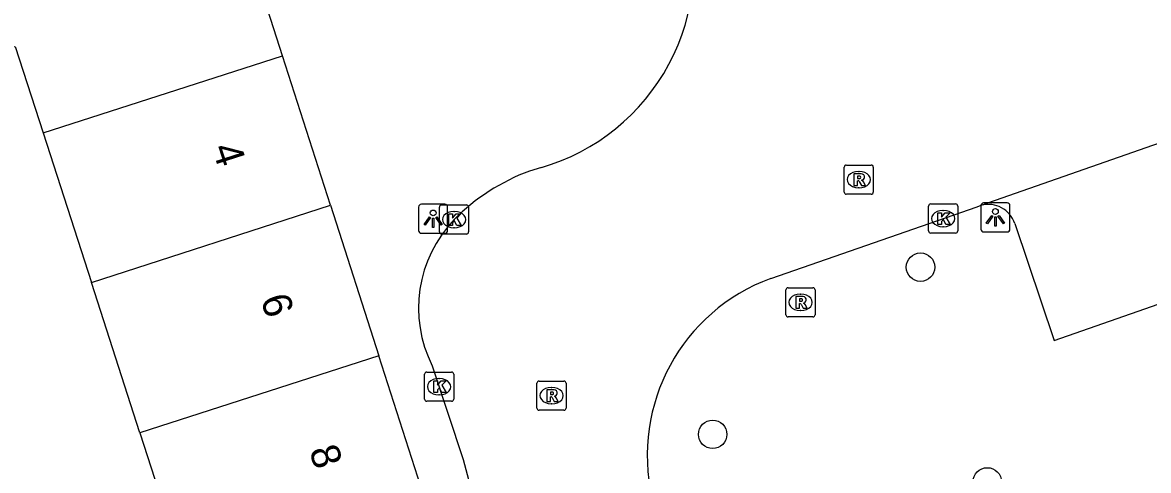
# Model space of a CAD drawing. Extents: x 159377 to 159983, y 382996 to 383595.
# Drawn here: x 159562.92 to 159601.57, y 383270.37 to 383285.73 of the extents above; entities that cross this region are included whole.
import ezdxf

# ---------------------------------------------------------------- set-up
doc = ezdxf.new("R2010")
doc.units = 0
for name, color, linetype in [('IMGEO_Boom', 7, 'Continuous'), ('IMGEO_Kolk', 7, 'Continuous'), ('IMGEO_Lichtpunt', 7, 'Continuous'), ('IMGEO_Pand', 7, 'Continuous'), ('IMGEO_Pand_nummerreeks', 7, 'Continuous'), ('IMGEO_Rijbaan_lokaal_open', 7, 'Continuous'), ('IMGEO_Rioolput', 7, 'Continuous'), ('IMGEO_Voetpad_open', 7, 'Continuous')]:
    doc.layers.add(name, color=color, linetype=linetype)

msp = doc.modelspace()

# ---------------------------------------------------------------- linework, layer by layer
at = {"layer": 'IMGEO_Boom'}
for centre in [(159593.747, 383277.342), (159586.612, 383271.606), (159596.038, 383269.973)]:
    msp.add_circle(centre, 0.489, dxfattribs=at)
at = {"layer": 'IMGEO_Kolk'}
for p, q in [((159577.307, 383279.475), (159578.159, 383279.475)), ((159594.024, 383278.583), (159594.024, 383279.435)), ((159594.099, 383279.509), (159594.951, 383279.509)), ((159595.025, 383279.435), (159595.025, 383278.583)), ((159577.232, 383278.549), (159577.232, 383279.401)), ((159577.72, 383279.255), (159577.745, 383279.255)), ((159578.233, 383279.401), (159578.233, 383278.549)), ((159594.512, 383279.289), (159594.537, 383279.289)), ((159577.743, 383278.695), (159577.718, 383278.695)), ((159594.535, 383278.729), (159594.51, 383278.729)), ((159578.159, 383278.475), (159577.307, 383278.475)), ((159594.951, 383278.509), (159594.099, 383278.509)), ((159576.72, 383272.814), (159576.72, 383273.666)), ((159576.795, 383273.74), (159577.647, 383273.74)), ((159577.721, 383273.666), (159577.721, 383272.814)), ((159577.208, 383273.52), (159577.233, 383273.52)), ((159577.231, 383272.96), (159577.206, 383272.96)), ((159577.647, 383272.74), (159576.795, 383272.74))]:
    msp.add_line(p, q, dxfattribs=at)
for points in [[(159577.307, 383279.475), (159578.159, 383279.475)], [(159594.024, 383278.583), (159594.024, 383279.435)], [(159594.099, 383279.509), (159594.951, 383279.509)], [(159595.025, 383279.435), (159595.025, 383278.583)], [(159577.232, 383278.549), (159577.232, 383279.401)], [(159577.553, 383279.175), (159577.676, 383279.175), (159577.676, 383279.024), (159577.806, 383279.175), (159577.97, 383279.175), (159577.824, 383279.024), (159577.977, 383278.775), (159577.825, 383278.775), (159577.74, 383278.939), (159577.676, 383278.872), (159577.676, 383278.775), (159577.553, 383278.775), (159577.553, 383279.175)], [(159578.233, 383279.401), (159578.233, 383278.549)], [(159594.345, 383279.209), (159594.468, 383279.209), (159594.468, 383279.058), (159594.598, 383279.209), (159594.762, 383279.209), (159594.616, 383279.058), (159594.769, 383278.809), (159594.617, 383278.809), (159594.532, 383278.973), (159594.468, 383278.906), (159594.468, 383278.809), (159594.345, 383278.809), (159594.345, 383279.209)], [(159578.159, 383278.475), (159577.307, 383278.475)], [(159594.951, 383278.509), (159594.099, 383278.509)], [(159576.72, 383272.814), (159576.72, 383273.666)], [(159576.795, 383273.74), (159577.647, 383273.74)], [(159577.721, 383273.666), (159577.721, 383272.814)], [(159577.041, 383273.44), (159577.164, 383273.44), (159577.164, 383273.289), (159577.294, 383273.44), (159577.458, 383273.44), (159577.312, 383273.289), (159577.465, 383273.04), (159577.313, 383273.04), (159577.228, 383273.204), (159577.164, 383273.137), (159577.164, 383273.04), (159577.041, 383273.04), (159577.041, 383273.44)], [(159577.647, 383272.74), (159576.795, 383272.74)]]:
    msp.add_lwpolyline(points, dxfattribs=at)
for centre, start, end in [((159577.309, 383279.399), 91.552, 178.448), ((159577.309, 383279.399), 91.552, 178.448), ((159578.157, 383279.399), 1.552, 88.448), ((159578.157, 383279.399), 1.552, 88.448), ((159594.101, 383279.433), 91.552, 178.448), ((159594.101, 383279.433), 91.552, 178.448), ((159594.949, 383279.433), 1.552, 88.448), ((159594.949, 383279.433), 1.552, 88.448), ((159577.309, 383278.551), 181.552, 268.448), ((159577.309, 383278.551), 181.552, 268.448), ((159578.157, 383278.551), 271.552, 358.448), ((159578.157, 383278.551), 271.552, 358.448), ((159594.101, 383278.585), 181.552, 268.448), ((159594.101, 383278.585), 181.552, 268.448), ((159594.949, 383278.585), 271.552, 358.448), ((159594.949, 383278.585), 271.552, 358.448), ((159576.797, 383273.664), 91.552, 178.448), ((159576.797, 383273.664), 91.552, 178.448), ((159577.645, 383273.664), 1.552, 88.448), ((159577.645, 383273.664), 1.552, 88.448), ((159576.797, 383272.816), 181.552, 268.448), ((159576.797, 383272.816), 181.552, 268.448), ((159577.645, 383272.816), 271.552, 358.448), ((159577.645, 383272.816), 271.552, 358.448)]:
    msp.add_arc(centre, 0.0765, start, end, dxfattribs=at)
for centre, major_axis, ratio, start_param, end_param in [((159577.719, 383278.975), (-0.387, 0.002), 0.722429, 4.712389, 7.853982), ((159577.744, 383278.975), (-0.39, 0.002), 0.717154, 1.570796, 4.712389), ((159594.511, 383279.009), (-0.387, 0.002), 0.722429, 4.712389, 7.853982), ((159594.536, 383279.009), (-0.39, 0.002), 0.717154, 1.570796, 4.712389), ((159577.207, 383273.24), (-0.387, 0.002), 0.722429, 4.712389, 7.853982), ((159577.232, 383273.24), (-0.39, 0.002), 0.717154, 1.570796, 4.712389)]:
    msp.add_ellipse(centre, major_axis=major_axis, ratio=ratio, start_param=start_param, end_param=end_param, dxfattribs=at)
at = {"layer": 'IMGEO_Lichtpunt'}
for p, q in [((159577.418, 383279.499), (159576.61, 383279.499)), ((159577.418, 383279.499), (159576.61, 383279.499)), ((159595.819, 383279.452), (159595.819, 383278.645)), ((159595.819, 383279.452), (159595.819, 383278.645)), ((159596.721, 383279.547), (159595.913, 383279.547)), ((159596.721, 383279.547), (159595.913, 383279.547)), ((159596.815, 383278.645), (159596.815, 383279.452)), ((159596.815, 383278.645), (159596.815, 383279.452)), ((159576.516, 383279.404), (159576.516, 383278.597)), ((159576.516, 383279.404), (159576.516, 383278.597)), ((159577.512, 383278.597), (159577.512, 383279.404)), ((159577.512, 383278.597), (159577.512, 383279.404)), ((159576.61, 383278.503), (159577.418, 383278.503)), ((159576.61, 383278.503), (159577.418, 383278.503)), ((159595.913, 383278.551), (159596.721, 383278.551)), ((159595.913, 383278.551), (159596.721, 383278.551))]:
    msp.add_line(p, q, dxfattribs=at)
for points in [[(159576.89, 383279.068), (159576.929, 383279.04), (159576.741, 383278.778), (159576.703, 383278.805), (159576.89, 383279.068)], [(159577.102, 383279.04), (159577.14, 383279.067), (159577.327, 383278.805), (159577.288, 383278.777), (159577.102, 383279.04)], [(159596.193, 383279.116), (159596.232, 383279.088), (159596.044, 383278.826), (159596.006, 383278.853), (159596.193, 383279.116)], [(159596.295, 383279.068), (159596.342, 383279.068), (159596.342, 383278.746), (159596.295, 383278.746), (159596.295, 383279.068)], [(159596.405, 383279.088), (159596.443, 383279.115), (159596.63, 383278.853), (159596.591, 383278.825), (159596.405, 383279.088)], [(159576.992, 383279.02), (159577.039, 383279.02), (159577.039, 383278.698), (159576.992, 383278.698), (159576.992, 383279.02)]]:
    msp.add_lwpolyline(points, dxfattribs=at)
for centre in [(159577.015, 383279.202), (159596.318, 383279.25)]:
    msp.add_circle(centre, 0.0994, dxfattribs=at)
for centre, start, end in [((159576.61, 383279.404), 90, 180), ((159576.61, 383279.404), 90, 180), ((159577.418, 383279.404), 0, 90), ((159577.418, 383279.404), 0, 90), ((159595.913, 383279.452), 90, 180), ((159595.913, 383279.452), 90, 180), ((159596.721, 383279.452), 0, 90), ((159596.721, 383279.452), 0, 90), ((159595.913, 383278.645), 180, 270), ((159595.913, 383278.645), 180, 270), ((159596.721, 383278.645), 270, 0), ((159596.721, 383278.645), 270, 360), ((159576.61, 383278.597), 180, 270), ((159576.61, 383278.597), 180, 270), ((159577.418, 383278.597), 270, 0), ((159577.418, 383278.597), 270, 360)]:
    msp.add_arc(centre, 0.0946, start, end, dxfattribs=at)
at = {"layer": 'IMGEO_Pand'}
for points in [[(159571.843, 383284.598), (159570.124, 383289.948)], [(159560.137, 383286.727), (159560.895, 383284.428), (159562.668, 383284.918), (159563.625, 383281.952)], [(159563.625, 383281.952), (159571.843, 383284.598)], [(159573.492, 383279.466), (159571.843, 383284.598)], [(159563.625, 383281.952), (159565.282, 383276.82)], [(159565.282, 383276.82), (159573.492, 383279.466)], [(159573.492, 383279.466), (159575.151, 383274.304)], [(159566.947, 383271.661), (159565.282, 383276.82)], [(159575.151, 383274.304), (159566.947, 383271.661)], [(159576.801, 383269.171), (159575.151, 383274.304)], [(159566.947, 383271.661), (159568.603, 383266.531)]]:
    msp.add_lwpolyline(points, dxfattribs=at)
at = {"layer": 'IMGEO_Rijbaan_lokaal_open'}
for points in [[(159595.831, 383279.464), (159630.111, 383291.458)], [(159580.733, 383280.762), (159580.321, 383280.639)], [(159588.61, 383276.954), (159595.694, 383279.416), (159595.831, 383279.464)], [(159576.984, 383273.96), (159578.044, 383270.742), (159578.879, 383267.605)]]:
    msp.add_lwpolyline(points, dxfattribs=at)
for centre, radius, start, end in [((159578.704, 383287.742), 7.269, 286.2109, 17.3819), ((159582.878, 383273.818), 7.285, 110.5479, 134.9315), ((159580.896, 383275.939), 4.384, 136.1765, 206.8346), ((159590.818, 383270.893), 6.451, 110.0178, 193.0148)]:
    msp.add_arc(centre, radius, start, end, dxfattribs=at)
at = {"layer": 'IMGEO_Rioolput'}
for p, q in [((159591.125, 383279.92), (159591.125, 383280.772)), ((159591.2, 383280.846), (159592.052, 383280.846)), ((159591.613, 383280.626), (159591.638, 383280.626)), ((159592.126, 383280.772), (159592.126, 383279.92)), ((159592.052, 383279.846), (159591.2, 383279.846)), ((159591.636, 383280.066), (159591.611, 383280.066)), ((159589.127, 383275.709), (159589.127, 383276.561)), ((159589.202, 383276.635), (159590.054, 383276.635)), ((159589.615, 383276.415), (159589.64, 383276.415)), ((159590.128, 383276.561), (159590.128, 383275.709)), ((159590.054, 383275.635), (159589.202, 383275.635)), ((159589.638, 383275.855), (159589.613, 383275.855)), ((159580.579, 383272.509), (159580.579, 383273.361)), ((159580.654, 383273.435), (159581.506, 383273.435)), ((159581.58, 383273.361), (159581.58, 383272.509)), ((159581.067, 383273.215), (159581.092, 383273.215)), ((159581.09, 383272.655), (159581.065, 383272.655)), ((159581.506, 383272.435), (159580.654, 383272.435))]:
    msp.add_line(p, q, dxfattribs=at)
for points in [[(159591.125, 383279.92), (159591.125, 383280.772)], [(159591.2, 383280.846), (159592.052, 383280.846)], [(159592.126, 383280.772), (159592.126, 383279.92)], [(159591.714, 383280.544), (159591.462, 383280.546), (159591.462, 383280.146)], [(159591.462, 383280.146), (159591.586, 383280.146), (159591.586, 383280.308), (159591.597, 383280.308)], [(159591.64, 383280.465), (159591.586, 383280.465), (159591.586, 383280.384)], [(159591.586, 383280.384), (159591.638, 383280.384)], [(159591.644, 383280.279), (159591.715, 383280.146), (159591.855, 383280.146), (159591.79, 383280.272)], [(159592.052, 383279.846), (159591.2, 383279.846)], [(159589.127, 383275.709), (159589.127, 383276.561)], [(159589.202, 383276.635), (159590.054, 383276.635)], [(159589.716, 383276.333), (159589.464, 383276.335), (159589.464, 383275.935)], [(159590.128, 383276.561), (159590.128, 383275.709)], [(159589.464, 383275.935), (159589.588, 383275.935), (159589.588, 383276.097), (159589.599, 383276.097)], [(159589.642, 383276.254), (159589.588, 383276.254), (159589.588, 383276.173)], [(159589.588, 383276.173), (159589.64, 383276.173)], [(159589.646, 383276.068), (159589.717, 383275.935), (159589.857, 383275.935), (159589.792, 383276.061)], [(159590.054, 383275.635), (159589.202, 383275.635)], [(159580.579, 383272.509), (159580.579, 383273.361)], [(159580.654, 383273.435), (159581.506, 383273.435)], [(159581.58, 383273.361), (159581.58, 383272.509)], [(159581.168, 383273.133), (159580.916, 383273.135), (159580.916, 383272.735)], [(159580.916, 383272.735), (159581.04, 383272.735), (159581.04, 383272.897), (159581.051, 383272.897)], [(159581.094, 383273.054), (159581.04, 383273.054), (159581.04, 383272.973)], [(159581.04, 383272.973), (159581.092, 383272.973)], [(159581.098, 383272.868), (159581.169, 383272.735), (159581.309, 383272.735), (159581.244, 383272.861)], [(159581.506, 383272.435), (159580.654, 383272.435)]]:
    msp.add_lwpolyline(points, dxfattribs=at)
for centre, radius, start, end in [((159591.202, 383280.77), 0.0765, 91.552, 178.448), ((159591.202, 383280.77), 0.0765, 91.552, 178.448), ((159592.05, 383280.77), 0.0765, 1.552, 88.448), ((159592.05, 383280.77), 0.0765, 1.552, 88.448), ((159591.596, 383280.255), 0.0533, 26.0293, 88.6989), ((159591.622, 383280.573), 0.19, 274.7715, 282.9687), ((159591.646, 383280.369), 0.0964, 77.0061, 93.1865), ((159591.66, 383280.426), 0.0378, 276.6634, 79.6772), ((159591.713, 383280.434), 0.109, 350.3612, 89.416), ((159591.711, 383280.434), 0.112, 277.5842, 350.9817), ((159591.695, 383280.219), 0.108, 29.5134, 73.7905), ((159591.202, 383279.922), 0.0765, 181.552, 268.448), ((159591.202, 383279.922), 0.0765, 181.552, 268.448), ((159592.05, 383279.922), 0.0765, 271.552, 358.448), ((159592.05, 383279.922), 0.0765, 271.552, 358.448), ((159589.204, 383276.559), 0.0765, 91.552, 178.448), ((159589.204, 383276.559), 0.0765, 91.552, 178.448), ((159589.715, 383276.223), 0.109, 350.3612, 89.416), ((159590.052, 383276.559), 0.0765, 1.552, 88.448), ((159590.052, 383276.559), 0.0765, 1.552, 88.448), ((159589.598, 383276.044), 0.0533, 26.0293, 88.6989), ((159589.624, 383276.362), 0.19, 274.7715, 282.9687), ((159589.648, 383276.158), 0.0964, 77.0061, 93.1865), ((159589.662, 383276.215), 0.0378, 276.6634, 79.6772), ((159589.713, 383276.223), 0.112, 277.5842, 350.9817), ((159589.697, 383276.008), 0.108, 29.5134, 73.7905), ((159589.204, 383275.711), 0.0765, 181.552, 268.448), ((159589.204, 383275.711), 0.0765, 181.552, 268.448), ((159590.052, 383275.711), 0.0765, 271.552, 358.448), ((159590.052, 383275.711), 0.0765, 271.552, 358.448), ((159580.656, 383273.359), 0.0765, 91.552, 178.448), ((159580.656, 383273.359), 0.0765, 91.552, 178.448), ((159581.504, 383273.359), 0.0765, 1.552, 88.448), ((159581.504, 383273.359), 0.0765, 1.552, 88.448), ((159581.05, 383272.844), 0.0533, 26.0293, 88.6989), ((159581.076, 383273.162), 0.19, 274.7715, 282.9687), ((159581.1, 383272.958), 0.0964, 77.0061, 93.1865), ((159581.114, 383273.015), 0.0378, 276.6634, 79.6772), ((159581.167, 383273.023), 0.109, 350.3612, 89.416), ((159581.165, 383273.023), 0.112, 277.5842, 350.9817), ((159581.149, 383272.808), 0.108, 29.5134, 73.7905), ((159580.656, 383272.511), 0.0765, 181.552, 268.448), ((159580.656, 383272.511), 0.0765, 181.552, 268.448), ((159581.504, 383272.511), 0.0765, 271.552, 358.448), ((159581.504, 383272.511), 0.0765, 271.552, 358.448)]:
    msp.add_arc(centre, radius, start, end, dxfattribs=at)
for centre, major_axis, ratio, start_param, end_param in [((159591.612, 383280.346), (-0.387, 0.002), 0.722429, 4.712389, 7.853982), ((159591.637, 383280.346), (-0.39, 0.002), 0.717154, 1.570796, 4.712389), ((159589.614, 383276.135), (-0.387, 0.002), 0.722429, 4.712389, 7.853982), ((159589.639, 383276.135), (-0.39, 0.002), 0.717154, 1.570796, 4.712389), ((159581.066, 383272.935), (-0.387, 0.002), 0.722429, 4.712389, 7.853982), ((159581.091, 383272.935), (-0.39, 0.002), 0.717154, 1.570796, 4.712389)]:
    msp.add_ellipse(centre, major_axis=major_axis, ratio=ratio, start_param=start_param, end_param=end_param, dxfattribs=at)
at = {"layer": 'IMGEO_Voetpad_open'}
msp.add_lwpolyline([(159596.981, 383278.836), (159598.339, 383274.831), (159630.904, 383286.196), (159629.509, 383290.184)], dxfattribs=at)
msp.add_arc((159596.076, 383278.545), 0.951, 17.8021, 104.9211, dxfattribs=at)

# ---------------------------------------------------------------- texts
at = {"layer": 'IMGEO_Pand_nummerreeks'}
for s, p in [('4', (159569.416, 383281.43)), ('6', (159571.082, 383276.246)), ('8', (159572.75, 383271.058))]:
    msp.add_text(s, height=1, rotation=287.815, dxfattribs=at).set_placement(p)

doc.saveas('drawing.dxf')
